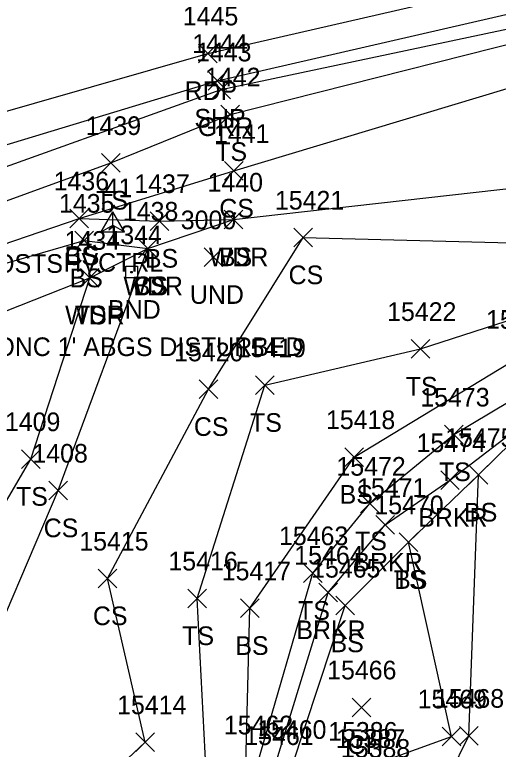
# Model space of a CAD drawing. Extents: x 1606530 to 1613020, y 784959 to 789666.
# Drawn here: x 1609101.2 to 1609153.1, y 788335.5 to 788414.2 of the extents above; entities that cross this region are included whole.
import ezdxf

# ---------------------------------------------------------------- set-up
doc = ezdxf.new("R2010")
doc.units = 0
for name, color, linetype in [('C_A', 7, 'Continuous'), ('C_I', 7, 'Continuous'), ('CPSM', 7, 'Continuous'), ('D_A', 7, 'Continuous'), ('D_I', 7, 'Continuous'), ('D_TIC', 7, 'Continuous'), ('L_A', 7, 'Continuous'), ('L_I', 7, 'Continuous'), ('L_TIC', 7, 'Continuous'), ('LAWA', 7, 'Continuous'), ('LAWE', 7, 'Continuous'), ('LELB', 7, 'Continuous'), ('M_A', 7, 'Continuous'), ('M_C', 7, 'Continuous'), ('M_I', 7, 'Continuous'), ('MHBP', 7, 'Continuous'), ('P_A', 7, 'Continuous'), ('P_I', 7, 'Continuous'), ('P_TIC', 7, 'Continuous'), ('PET', 7, 'Continuous'), ('PSP', 7, 'Continuous'), ('R_A', 7, 'Continuous'), ('R_C', 7, 'Continuous'), ('R_I', 7, 'Continuous'), ('R_TIC', 7, 'Continuous'), ('RGR', 7, 'Continuous')]:
    doc.layers.add(name, color=color, linetype=linetype)

msp = doc.modelspace()

# ---------------------------------------------------------------- linework, layer by layer
at = {"layer": 'CPSM'}
for p, q in [((1609110.473, 788390.947), (1609111.723, 788393.112)), ((1609112.973, 788390.947), (1609111.723, 788393.112)), ((1609111.724, 788391.668), (1609111.723, 788393.112)), ((1609110.473, 788390.947), (1609111.724, 788391.668)), ((1609111.724, 788391.668), (1609111.724, 788391.668)), ((1609111.724, 788391.668), (1609112.973, 788390.947)), ((1609110.473, 788390.947), (1609112.973, 788390.947))]:
    msp.add_line(p, q, dxfattribs=at)
at = {"layer": 'D_TIC'}
for points in [[(1609121.506, 788387.228), (1609123.506, 788389.228)], [(1609123.506, 788387.228), (1609121.506, 788389.228)]]:
    msp.add_lwpolyline(points, dxfattribs=at)
at = {"layer": 'L_TIC'}
for points in [[(1609123.294, 788402.549), (1609125.294, 788404.549)], [(1609125.294, 788402.549), (1609123.294, 788404.549)], [(1609110.494, 788397.335), (1609112.494, 788399.335)], [(1609112.494, 788397.335), (1609110.494, 788399.335)], [(1609123.693, 788396.484), (1609125.693, 788398.484)], [(1609125.693, 788396.484), (1609123.693, 788398.484)], [(1609107.106, 788391.394), (1609109.106, 788393.394)], [(1609109.106, 788391.394), (1609107.106, 788393.394)], [(1609107.106, 788391.394), (1609109.106, 788393.394)], [(1609109.106, 788391.394), (1609107.106, 788393.394)], [(1609115.71, 788391.112), (1609117.71, 788393.112)], [(1609117.71, 788391.112), (1609115.71, 788393.112)], [(1609123.652, 788391.268), (1609125.652, 788393.268)], [(1609125.652, 788391.268), (1609123.652, 788393.268)], [(1609123.652, 788391.268), (1609125.652, 788393.268)], [(1609125.652, 788391.268), (1609123.652, 788393.268)], [(1609107.627, 788389.006), (1609109.627, 788391.006)], [(1609109.627, 788389.006), (1609107.627, 788391.006)], [(1609131.129, 788389.339), (1609133.129, 788391.339)], [(1609133.129, 788389.339), (1609131.129, 788391.339)], [(1609114.481, 788388.157), (1609116.481, 788390.157)], [(1609116.481, 788388.157), (1609114.481, 788390.157)], [(1609114.481, 788388.157), (1609116.481, 788390.157)], [(1609116.481, 788388.157), (1609114.481, 788390.157)], [(1609114.481, 788388.157), (1609116.481, 788390.157)], [(1609116.481, 788388.157), (1609114.481, 788390.157)], [(1609108.225, 788385.029), (1609110.225, 788387.029)], [(1609110.225, 788385.029), (1609108.225, 788387.029)], [(1609108.225, 788385.029), (1609110.225, 788387.029)], [(1609110.225, 788385.029), (1609108.225, 788387.029)], [(1609143.734, 788377.396), (1609145.734, 788379.396)], [(1609145.734, 788377.396), (1609143.734, 788379.396)], [(1609120.968, 788373.067), (1609122.968, 788375.067)], [(1609122.968, 788373.067), (1609120.968, 788375.067)], [(1609127.026, 788373.505), (1609129.026, 788375.505)], [(1609129.026, 788373.505), (1609127.026, 788375.505)], [(1609147.296, 788368.221), (1609149.296, 788370.221)], [(1609149.296, 788368.221), (1609147.296, 788370.221)], [(1609101.909, 788365.579), (1609103.909, 788367.579)], [(1609103.909, 788365.579), (1609101.909, 788367.579)], [(1609136.603, 788365.797), (1609138.603, 788367.797)], [(1609138.603, 788365.797), (1609136.603, 788367.797)], [(1609149.966, 788363.886), (1609151.966, 788365.886)], [(1609151.966, 788363.886), (1609149.966, 788365.886)], [(1609149.966, 788363.886), (1609151.966, 788365.886)], [(1609151.966, 788363.886), (1609149.966, 788365.886)], [(1609146.892, 788363.328), (1609148.892, 788365.328)], [(1609148.892, 788363.328), (1609146.892, 788365.328)], [(1609104.849, 788362.204), (1609106.849, 788364.204)], [(1609106.849, 788362.204), (1609104.849, 788364.204)], [(1609138.293, 788360.805), (1609140.293, 788362.805)], [(1609140.293, 788360.805), (1609138.293, 788362.805)], [(1609139.944, 788358.529), (1609141.944, 788360.529)], [(1609141.944, 788358.529), (1609139.944, 788360.529)], [(1609142.455, 788356.666), (1609144.455, 788358.666)], [(1609144.455, 788356.666), (1609142.455, 788358.666)], [(1609142.455, 788356.666), (1609144.455, 788358.666)], [(1609144.455, 788356.666), (1609142.455, 788358.666)], [(1609132.179, 788353.353), (1609134.179, 788355.353)], [(1609134.179, 788353.353), (1609132.179, 788355.353)], [(1609110.131, 788352.774), (1609112.131, 788354.774)], [(1609112.131, 788352.774), (1609110.131, 788354.774)], [(1609133.818, 788351.275), (1609135.818, 788353.275)], [(1609135.818, 788351.275), (1609133.818, 788353.275)], [(1609119.749, 788350.638), (1609121.749, 788352.638)], [(1609121.749, 788350.638), (1609119.749, 788352.638)], [(1609125.42, 788349.584), (1609127.42, 788351.584)], [(1609127.42, 788349.584), (1609125.42, 788351.584)], [(1609135.628, 788349.872), (1609137.628, 788351.872)], [(1609137.628, 788349.872), (1609135.628, 788351.872)], [(1609137.402, 788338.96), (1609139.402, 788340.96)], [(1609139.402, 788338.96), (1609137.402, 788340.96)], [(1609148.902, 788335.919), (1609150.902, 788337.919)], [(1609150.902, 788335.919), (1609148.902, 788337.919)], [(1609114.192, 788335.223), (1609116.192, 788337.223)], [(1609116.192, 788335.223), (1609114.192, 788337.223)], [(1609147.062, 788335.849), (1609149.062, 788337.849)], [(1609149.062, 788335.849), (1609147.062, 788337.849)]]:
    msp.add_lwpolyline(points, dxfattribs=at)
at = {"layer": 'LAWA'}
msp.add_lwpolyline([(1609030.558, 788292.644), (1609056.025, 788324.438), (1609082.563, 788354.607), (1609090.163, 788369.421), (1609097.263, 788381.318), (1609109.225, 788386.029), (1609115.481, 788389.157), (1609124.652, 788392.268), (1609168.817, 788397.242), (1609199.024, 788403.22), (1609247.618, 788406.183), (1609289.075, 788410.022), (1609331.313, 788409.888), (1609380.075, 788411.965), (1609422.468, 788410.639), (1609441.897, 788412.637), (1609456.944, 788393.193), (1609459.972, 788389.839), (1609451.94, 788379.298), (1609445.608, 788371.597)], dxfattribs=at)
at = {"layer": 'LAWE'}
msp.add_lwpolyline([(1609173.649, 788240.676), (1609157.566, 788256.298), (1609146.796, 788268.872), (1609140.112, 788290.968), (1609139.76, 788302.754), (1609129.692, 788311.813), (1609128.89, 788332.921), (1609134.818, 788352.275), (1609140.944, 788359.529), (1609147.892, 788364.328), (1609159.94, 788373.535), (1609169.272, 788374.834), (1609179.539, 788381.792), (1609181.941, 788380.544), (1609177.684, 788370.102), (1609176.3, 788365.897)], dxfattribs=at)
at = {"layer": 'LELB'}
for points in [[(1608830.696, 788263.063), (1608870.165, 788285.39), (1608903.607, 788303.663), (1608913.174, 788310.86), (1608944.686, 788327.514), (1608982.087, 788348.333), (1609025.652, 788367.839), (1609062.434, 788383.436), (1609080.361, 788388.448), (1609093.562, 788391.85), (1609111.494, 788398.335), (1609124.294, 788403.549), (1609165.327, 788413.887), (1609196.534, 788419.382), (1609241.91, 788424.939), (1609287.826, 788428.62), (1609331.16, 788428.802), (1609379.004, 788428.227), (1609424.692, 788425.716), (1609443.901, 788424.449), (1609475.845, 788418.568), (1609486.477, 788419.986), (1609502.626, 788421.703)], [(1609108.106, 788392.394), (1609124.693, 788397.484), (1609165.899, 788409.884), (1609197.342, 788410.752), (1609242.015, 788420.69), (1609288.516, 788423.98), (1609330.866, 788426.644), (1609378.664, 788424.919), (1609423.799, 788422.523), (1609442.786, 788421.027), (1609475.941, 788416.786), (1609485.224, 788416.477)], [(1608831.711, 788260.016), (1608870.917, 788283.544), (1608902.903, 788300.531), (1608905.174, 788302.06), (1608913.863, 788309.861), (1608916.937, 788311.145), (1608945.63, 788325.493), (1608982.977, 788345.361), (1609026.683, 788366.486), (1609062.425, 788381.051), (1609095.627, 788388.111), (1609108.106, 788392.394), (1609116.71, 788392.112), (1609124.652, 788392.268)], [(1609065.635, 788267.334), (1609081.959, 788290.895), (1609101.735, 788313.342), (1609121.944, 788328.842), (1609120.749, 788351.638), (1609128.026, 788374.505), (1609144.734, 788378.396), (1609178.081, 788389.176), (1609191.957, 788391.406), (1609197.675, 788378.651), (1609184.805, 788360.047), (1609179.632, 788359.129)], [(1608916.937, 788311.145), (1608917.754, 788309.334), (1608946.535, 788323.696), (1608983.532, 788344.076), (1609027.167, 788365.399), (1609062.769, 788379.31), (1609096.646, 788386.547), (1609108.627, 788390.006), (1609115.481, 788389.157)], [(1609053.661, 788273.38), (1609077.554, 788293.594), (1609095.849, 788318.069), (1609115.192, 788336.223), (1609111.131, 788353.774), (1609121.968, 788374.067), (1609132.129, 788390.339), (1609178.081, 788389.176)], [(1609044.685, 788283.597), (1609058.258, 788305.111), (1609096.979, 788342.471), (1609105.849, 788363.204), (1609115.481, 788389.157)], [(1609038.437, 788287.942), (1609056.526, 788316.096), (1609093.182, 788350), (1609102.909, 788366.579), (1609109.225, 788386.029)], [(1609081.227, 788263.396), (1609089.388, 788281.947), (1609107.582, 788302.227), (1609121.692, 788312.329), (1609125.649, 788321.256), (1609126.42, 788350.584), (1609137.603, 788366.797), (1609155.353, 788377.552), (1609174.448, 788383.669)], [(1609127.265, 788334.063), (1609133.179, 788354.353), (1609139.293, 788361.805), (1609148.296, 788369.221), (1609160.171, 788376.296), (1609170.08, 788379.145), (1609174.448, 788383.669), (1609187.933, 788379.477), (1609182.76, 788370.408), (1609179.632, 788359.129), (1609171.894, 788353.175), (1609164.852, 788341.255), (1609162.757, 788324.685)], [(1609174.197, 788240.789), (1609158.083, 788257.445), (1609147.39, 788269.582), (1609141.257, 788291.021), (1609140.389, 788303.272), (1609130.327, 788311.971), (1609130.919, 788333.577), (1609136.628, 788350.872), (1609143.455, 788357.666), (1609150.966, 788364.886), (1609158.145, 788371.934), (1609169.438, 788373.414), (1609179.539, 788381.792)], [(1609149.902, 788336.919), (1609150.966, 788364.886)], [(1609148.062, 788336.849), (1609143.455, 788357.666)], [(1609138.462, 788333.382), (1609148.062, 788336.849)], [(1609145.831, 788328.626), (1609149.902, 788336.919)]]:
    msp.add_lwpolyline(points, dxfattribs=at)
at = {"layer": 'MHBP'}
msp.add_lwpolyline([(1609113.091, 788387.254), (1609114.341, 788387.254), (1609114.341, 788386.004), (1609113.091, 788386.004)], close=True, dxfattribs=at)
msp.add_circle((1609113.716, 788386.629), 0.0833, dxfattribs=at)
at = {"layer": 'P_TIC'}
for points in [[(1609120.915, 788409.089), (1609122.915, 788411.089)], [(1609122.915, 788409.089), (1609120.915, 788411.089)], [(1609121.924, 788406.129), (1609123.924, 788408.129)], [(1609123.924, 788406.129), (1609121.924, 788408.129)]]:
    msp.add_lwpolyline(points, dxfattribs=at)
at = {"layer": 'PET'}
msp.add_lwpolyline([(1608827.199, 788266.245), (1608867.859, 788290.541), (1608906.681, 788312.856), (1608942.677, 788332.755), (1608980.541, 788352.164), (1609023.571, 788373.225), (1609061.437, 788389.904), (1609090.798, 788401.175), (1609121.915, 788410.089), (1609165.169, 788419.998), (1609195.853, 788425.54), (1609240.139, 788431.13), (1609287.877, 788434.372), (1609331.481, 788435.115), (1609378.889, 788434.051), (1609425.427, 788432.251), (1609443.83, 788431.331), (1609477.321, 788429.782), (1609518.441, 788427.602), (1609569.185, 788424.684), (1609602.993, 788422.58), (1609641.45, 788420.372), (1609681.697, 788417.919), (1609727.381, 788415.531)], dxfattribs=at)
at = {"layer": 'PSP'}
msp.add_lwpolyline([(1608830.356, 788264.996), (1608869.22, 788287.395), (1608908.593, 788309.539), (1608943.858, 788329.41), (1608981.495, 788349.27), (1609025.121, 788370.206), (1609061.921, 788386.228), (1609076.386, 788391.443), (1609089.956, 788397.157), (1609122.924, 788407.129), (1609165.713, 788417.027), (1609196.423, 788422.444), (1609241.306, 788428.683), (1609287.876, 788431.577), (1609331.197, 788431.668), (1609378.916, 788430.276), (1609425.006, 788428.307)], dxfattribs=at)
at = {"layer": 'R_TIC'}
for points in [[(1609122.333, 788405.226), (1609124.333, 788407.226)], [(1609124.333, 788405.226), (1609122.333, 788407.226)]]:
    msp.add_lwpolyline(points, dxfattribs=at)
at = {"layer": 'RGR'}
msp.add_lwpolyline([(1609093.559, 788395.554), (1609123.333, 788406.226), (1609196.194, 788421.651), (1609241.24, 788427.813), (1609287.728, 788430.927), (1609331.285, 788431.083), (1609378.856, 788429.586), (1609425.051, 788427.72), (1609442.608, 788426.228), (1609477.202, 788421.475)], dxfattribs=at)

# ---------------------------------------------------------------- texts
at = {"layer": 'C_A'}
msp.add_text('HVCTRL', height=2, dxfattribs=at).set_placement((1609106.417, 788386.668))
at = {"layer": 'C_I'}
msp.add_text('41', height=2, dxfattribs=at).set_placement((1609110.826, 788394.668))
at = {"layer": 'D_A'}
msp.add_text('UND', height=2, dxfattribs=at).set_placement((1609119.979, 788383.228))
at = {"layer": 'D_I'}
msp.add_text('3000', height=2, dxfattribs=at).set_placement((1609119.002, 788391.228))
at = {"layer": 'L_A'}
for s, p in [('TS', (1609122.704, 788398.549)), ('TS', (1609109.903, 788393.335)), ('CS', (1609123.134, 788392.484)), ('CS', (1609106.547, 788387.394)), ('BS', (1609106.547, 788387.394)), ('BS', (1609115.151, 788387.112)), ('WDR', (1609122.014, 788387.268)), ('BS', (1609123.093, 788387.268)), ('BS', (1609107.068, 788385.006)), ('CS', (1609130.569, 788385.339)), ('WDR', (1609112.844, 788384.157)), ('CS', (1609113.922, 788384.157)), ('BS', (1609113.922, 788384.157)), ('WDR', (1609106.587, 788381.029)), ('TS', (1609107.635, 788381.029)), ('TS', (1609143.144, 788373.396)), ('CS', (1609120.409, 788369.067)), ('TS', (1609126.435, 788369.505)), ('TS', (1609146.706, 788364.221)), ('TS', (1609101.318, 788361.579)), ('BS', (1609136.044, 788361.797)), ('BS', (1609149.407, 788359.886)), ('BS', (1609149.407, 788359.886)), ('BRKR', (1609144.482, 788359.328)), ('CS', (1609104.29, 788358.204)), ('TS', (1609137.703, 788356.805)), ('BRKR', (1609137.534, 788354.529)), ('TS', (1609141.865, 788352.666)), ('BS', (1609141.896, 788352.666)), ('TS', (1609131.588, 788349.353)), ('CS', (1609109.572, 788348.774)), ('BRKR', (1609131.408, 788347.275)), ('TS', (1609119.159, 788346.638)), ('BS', (1609124.861, 788345.584)), ('BS', (1609135.069, 788345.872)), ('CH', (1609136.89, 788334.96))]:
    msp.add_text(s, height=2, dxfattribs=at).set_placement(p)
at = {"layer": 'L_I'}
for s, p in [('1442', (1609121.602, 788406.549)), ('1439', (1609108.793, 788401.335)), ('1441', (1609122.567, 788400.484)), ('1436', (1609105.358, 788395.394)), ('1436', (1609105.358, 788395.394)), ('1437', (1609114.017, 788395.112)), ('1440', (1609121.873, 788395.268)), ('1440', (1609121.873, 788395.268)), ('1435', (1609105.934, 788393.006)), ('15421', (1609129.105, 788393.339)), ('1438', (1609112.789, 788392.157)), ('1438', (1609112.789, 788392.157)), ('1438', (1609112.789, 788392.157)), ('1434', (1609106.533, 788389.029)), ('1434', (1609106.533, 788389.029)), ('15422', (1609141.144, 788381.396)), ('15423', (1609151.762, 788380.552)), ('15420', (1609118.291, 788377.067)), ('15419', (1609124.995, 788377.505)), ('15473', (1609144.706, 788372.221)), ('15418', (1609134.58, 788369.797)), ('1409', (1609100.13, 788369.579)), ('15475', (1609147.375, 788367.886)), ('15475', (1609147.375, 788367.886)), ('15474', (1609144.301, 788367.328)), ('1408', (1609103.078, 788366.204)), ('15472', (1609135.703, 788364.805)), ('15471', (1609137.92, 788362.529)), ('15470', (1609139.778, 788360.666)), ('15470', (1609139.778, 788360.666)), ('15463', (1609129.541, 788357.353)), ('15415', (1609108.108, 788356.774)), ('15464', (1609131.18, 788355.275)), ('15416', (1609117.671, 788354.638)), ('15417', (1609123.397, 788353.584)), ('15465', (1609132.991, 788353.872)), ('15466', (1609134.709, 788342.96)), ('15469', (1609144.417, 788339.849)), ('15468', (1609146.265, 788339.919)), ('15414', (1609112.169, 788339.223)), ('15462', (1609123.627, 788337.063)), ('15461', (1609125.819, 788335.921)), ('15460', (1609127.194, 788336.577)), ('15386', (1609134.816, 788336.382)), ('15387', (1609135.637, 788335.614)), ('15388', (1609136.18, 788334.557))]:
    msp.add_text(s, height=2, dxfattribs=at).set_placement(p)
at = {"layer": 'M_A'}
msp.add_text('BND', height=2, dxfattribs=at).set_placement((1609111.204, 788381.629))
at = {"layer": 'M_C'}
msp.add_text("4X4 CONC 1' ABGS DISTURBED", height=2, dxfattribs=at).set_placement((1609091.677, 788377.629))
at = {"layer": 'M_I'}
msp.add_text('1344', height=2, dxfattribs=at).set_placement((1609111.023, 788389.629))
at = {"layer": 'P_A'}
for s, p in [('RDP', (1609119.403, 788405.089)), ('SHP', (1609120.46, 788402.129))]:
    msp.add_text(s, height=2, dxfattribs=at).set_placement(p)
at = {"layer": 'P_I'}
for s, p in [('1445', (1609119.222, 788413.089)), ('1444', (1609120.231, 788410.129))]:
    msp.add_text(s, height=2, dxfattribs=at).set_placement(p)
at = {"layer": 'R_A'}
msp.add_text('GRR', height=2, dxfattribs=at).set_placement((1609120.821, 788401.226))
at = {"layer": 'R_C'}
msp.add_text('SGR W/ WOOD POSTS', height=2, dxfattribs=at).set_placement((1609077.386, 788386.554))
at = {"layer": 'R_I'}
msp.add_text('1443', height=2, dxfattribs=at).set_placement((1609120.64, 788409.226))

doc.saveas('drawing.dxf')
